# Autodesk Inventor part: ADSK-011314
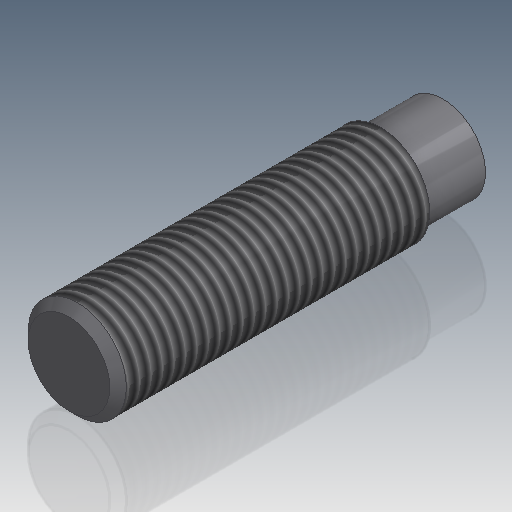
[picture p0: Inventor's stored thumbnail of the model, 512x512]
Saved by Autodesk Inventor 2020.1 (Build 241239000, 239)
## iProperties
Created: 1999-12
Part Number: ADSK-011314
Material: Acier doux
Description: SHFT-T,TH,CP,012,045,007,000,MNT,BEARING,TAILSHAFT
Document SubType Name: Modeling
Designer: tgregory
Density: 7.86 g/cm^3
Appearance: Metal-Steel(Polish)
Mass: 606.443 g
Surface Area: 117.982 cm^2
Volume: 77.1556 cm^3
Control State: 0
Checked Out: False
Last Check In By: sspink
Last Check In Date: 1999-12-22
Master: False
Shininess: 0.0
Length Units: 11269
Angle Units: 11279
Time Units: 11290
Mass Units: 11283
Length Display Precision: 3
Angle Display Precision: 2
Compacted: True
Dimensions: 30x30x114,3 mm
Mass: 0,606 kg
DocNumber: ADSK-011314.ipt
Folder: 01 - Themengebiete\Simplification\01 - Packaging machine\
VDS_Category: 3D Komponenten
Density: 0.0
Volumn: 0.0
Area: 0.0
PropertySet Name: Model Information
Author: tgregory
Revision Number: -
Title: SHFT-T,TH,CP,012,045,007,000,MNT,BEARING,TAILSHAFT
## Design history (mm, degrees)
node "Solide1"
  node "Extrusion1" dims "d1" = 114.3, "d2" = 0
  node "Extrusion2" dims "d4" = 19.05, "d5" = 0
sketch "Sketch1"
  geometry: C1 r 15 at (0, 0)
  constraints: 1 centre point, 1 other
  dimensions: "d0" = 30 diameter of C1
sketch "Sketch2"
  geometry: C1 r 15 at (0, 0) reference; C2 r 13 at (0, 0)
  constraints: 1 centre point, 1 coincident
  dimensions: "d3" = 26 diameter of C2
feature "Gewinde1" dims "d6" = 95.25, "d7" = 0
chamfer "Fase1" distance "d8" = 2.54; stored, may be unused: second distance "d9" = 3.175, angle "d10" = 45 deg
node "Corps solides"
node "Corps surfaciques"
